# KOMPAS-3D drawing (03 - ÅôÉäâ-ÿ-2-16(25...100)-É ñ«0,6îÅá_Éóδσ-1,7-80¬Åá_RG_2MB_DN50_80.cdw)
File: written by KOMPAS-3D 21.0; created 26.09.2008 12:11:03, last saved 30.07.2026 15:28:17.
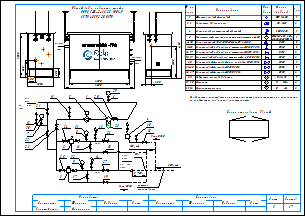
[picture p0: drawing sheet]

Sheets 1-2: A3, landscape

Document properties: Наименование: Макро:21; Автор: RaskoAdmin; Форматы листов документа: 2xA3; Полное имя файла: \\ur38nt01\Departments\КТО\КБ ПУРДГ\Заявки\Прайс-лист на типовые шкафы ГРПШ\ПУРДГ_стандарт_30_04_2026\ПУРДГ с RG_2MB\ПУРДГ-Ш-2-16(25...100)-Р до0,6МПа_Рвых-1,7-80кПа_RG_2MB_DN50_80.cdw

Title block, sheet 1: Наименование: Пункт учета газа / ПУГ-Ш-400-Р / ЛГТИ.485922.001ТУ; designation: ЛГТИ.03.4411141; sheet number: 1; Количество листов документа: 2; organisation: ООО "ЭЛЬСТЕР Газэлектроника"; Форматы листов документа: A3; stored path: C:\Рабочие документы\Компас\ПУГ\Схема.cdw; Разработал: Устинов; Проверил: Кошкин; Утвердил: Кошкин
Title block, sheet 2: sheet number: 2; stored path: D:\Рабочие документы\Заявки\ПУРДГ\ПУРДГ-ШУЭО-2-100-Р 4411220.cdw; designation, second copy: ЛГТИ.03.4411141-

Views: Вид 1, Вид 2
Referenced files: wcvoit.frw
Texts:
  Normal
  № на
  схеме
  Усл.
  обозн.
  Марка
  (модель)
  Кол.
  Фильтр газовый фланцевый
  ФГ 16-50
  Регулятор давления газа
  RG/2MB
  Клапан предохранительный сбросной
  КПС DN20
  Измерительный комплекс с ротационным счетчиком Ду50
  СГ-ЭК-Р-(0,2...2,0)-
  Кран кнопочный VE-РАСКО-НЗ-1,6-G1/2-М20
  DN15
  Кран шаровой "под приварку" штуцерный DN20 PN16
  DN20
  Кран шаровой "под приварку" штуцерный DN15 PN16
  Кран шаровой "под приварку" штуцерный п/п DN20 PN16
  Кран шаровой фланцевый с мех. приводом DN50 PN16
  Кран шаровой фланцевый DN50 PN16
  Кран шаровой фланцевый DN80 PN16
  DN50
  DN80
  Индикатор перепада давления
  Манометр
  Манометр-напоромер
  Delta 15
  0...     МПа
  0...     кПа
  Общий вид и габариты шкафа
  ПУРДГ-Ш-2-16(25...100)-Р
  Выход газа
  Вход газа
  logo-rasko-ge.png
  DN 1
  местное
  сопротивление
  Римп DN20
  Выход
  газа
  Р=     кПа
  Вход
  Р=       МПа
  PDI
  Схема открывания дверей
  Предприятие изготовитель может заменять комплектующие на аналогичные,
  не ухудшающие заявленных характеристик.
  Должность
  Конструктор
  Фамилия
  Подпись
  Дата
  Согласовано
  Максимкин
  Лист
  Листов
  POLYLINE_STYLE_0.18_RGB_0_0_0
  POLYLINE_STYLE_0.50_RGB_0_0_0
  POLYLINE_STYLE_0.34_RGB_0_0_0
  PHANTOM_RGB_0_0_0_SC_1_THICK_0.18
  K5LT_THIN_RGB_0_0_0_THICK_0.18
  K5LT32769_RGB_0_0_0_THICK_0.18
  K5LT12_RGB_0_0_0_SC_1_THICK_0.18
  K5LT_DASHED_RGB_0_0_0_SC_1_THICK_0.18
  ACISOTGL_RGB_0_0_0_SC_0.8_THICK_0.25
  CONTINUOUS_RGB_0_127_31_THICK_0.3
  CONTINUOUS_RGB_0_0_255_THICK_0.35
  CONTINUOUS_RGB_255_0_0_THICK_0.35
  POLYLINE_STYLE_0.25_RGB_0_0_0
  CONTINUOUS_RGB_0_0_0_THICK_0.5
  POLYLINE_STYLE_0.35_RGB_0_0_255
  CONTINUOUS_RGB_0_0_0_THICK_0.4
  CONTINUOUS_RGB_0_0_0_THICK_0.35
  НЕВИДИМАЯ_RGB_0_0_0_SC_0.3_THICK_0.25
  СONTINUOUS_RGB_0_0_0_THICK_0.25
  ОСЕВАЯ2_RGB_248_153_30_SC_0.3_THICK_0.25
  Без оформления
Dimensions and other numbers on the sheet: 1; 2, 3; 2; 4; 5; 6-10; 11-15; 16, 17; 18, 19; 20; 21-25; 26, 27; 28; 29, 30; 31, 32; 1500; 250; 300; 1050; 550; 305; 2300; 4130; 2000; 2600; 5,,,7DN 1; 7; 30; 12; 21; 22; 23; 11; 6; 29; 24; 31; 8; 16; 13; 26; 18; 10; 15; 25; 32; 9; 3; 17; 14; 27; 19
